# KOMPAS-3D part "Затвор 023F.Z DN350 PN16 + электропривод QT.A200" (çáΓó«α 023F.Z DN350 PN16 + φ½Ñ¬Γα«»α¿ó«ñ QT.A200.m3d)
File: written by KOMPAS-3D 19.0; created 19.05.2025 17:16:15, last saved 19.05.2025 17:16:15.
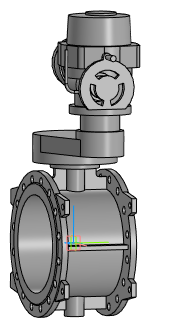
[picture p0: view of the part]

Document properties: Полное имя файла: Затвор 023F.Z DN350 PN16 + электропривод QT.A200.a3d

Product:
- Part/product: Затвор 023F.Z DN350 PN16 + электропривод QT.A200
    Масса: 357.078

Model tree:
1. Операция без истории:1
